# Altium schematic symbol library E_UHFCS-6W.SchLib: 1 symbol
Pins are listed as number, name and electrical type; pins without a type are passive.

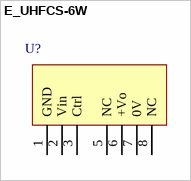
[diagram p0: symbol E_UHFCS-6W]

## E_UHFCS-6W
designator U?
footprint E_UHFCS-6W
pins: 1 GND, 2 Vin, 3 Ctrl, 5 NC, 6 +Vo, 7 0V, 8 NC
